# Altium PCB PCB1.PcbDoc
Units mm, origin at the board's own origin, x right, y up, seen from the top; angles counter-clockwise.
Board outline 143.51 x 21.34 mm, 2 copper layers (Top Layer, Bottom Layer); 100 components, 175 nets, 474 pads, 153 vias.
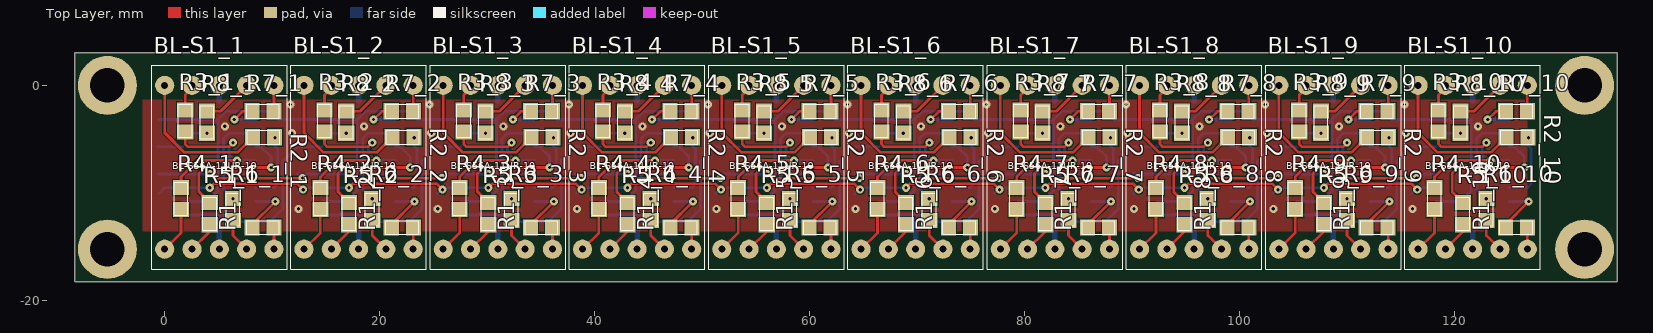
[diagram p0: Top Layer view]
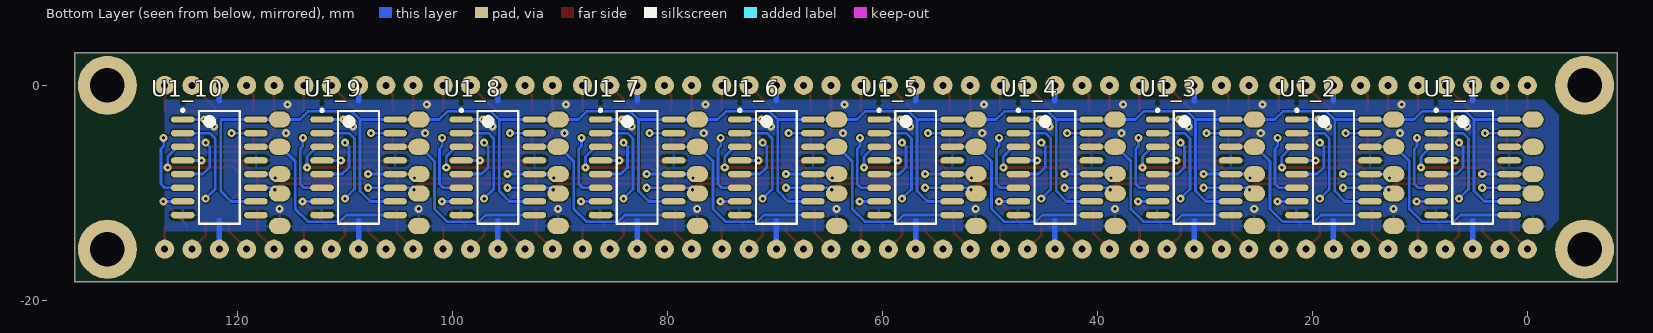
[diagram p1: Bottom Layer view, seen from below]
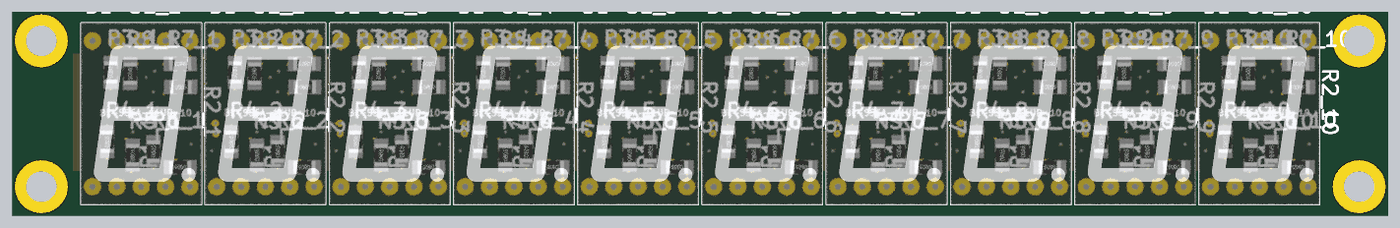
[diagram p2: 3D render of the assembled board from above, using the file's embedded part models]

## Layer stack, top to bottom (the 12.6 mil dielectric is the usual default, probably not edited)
Top Solder: solder mask 0.0102, Solder Resist, Dk 3.5
Top Layer: signal copper 0.0356
Dielectric 1: dielectric 0.32, FR-4, Dk 4.8
Bottom Layer: signal copper 0.0356
Bottom Solder: solder mask 0.0102, Solder Resist, Dk 3.5

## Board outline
-8.382,-18.288 -8.382,3.048 135.128,3.048 135.128,-18.288

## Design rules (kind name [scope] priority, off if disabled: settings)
Clearance [All] p1: gap=0.127
HoleSize [All] p1: absolutevalues=TRUE maxlimit=3.5 minlimit=0.025 maxpercent=80.000 minpercent=20.000
MinimumSolderMaskSliver [All] p1 off: minsoldermaskwidth=0.254
PolygonConnect toLEDS [HasFootprint('BL-S56A-11UR')] p1: connectstyle=Relief reliefconductorwidth=0.254 reliefentries=4 polygonreliefangle="45 Angle" airgapwidth=0.254
PolygonConnect toPADS [InPadClass('GND_PADS')] p2: connectstyle=Relief reliefconductorwidth=0.254 reliefentries=4 polygonreliefangle="90 Angle" airgapwidth=0.254
PolygonConnect toHC74 [HasFootprint('PRSP0016DH-B_N')] p3: connectstyle=Relief reliefconductorwidth=0.254 reliefentries=4 polygonreliefangle="90 Angle" airgapwidth=0.254
PolygonConnect [All] p4: connectstyle=Direct reliefconductorwidth=0.254 reliefentries=4 polygonreliefangle="90 Angle" airgapwidth=0.381
RoomDefinition 10 [InComponentClass('10')] p1: confinementstyle=ConfineIn formatcopy=TRUE lockcomponents=TRUE outline 114.935,-17.78 114.935,2.54 128.067,2.54 128.067,-17.78
RoomDefinition 9 [InComponentClass('9')] p2: confinementstyle=ConfineIn formatcopy=TRUE lockcomponents=TRUE outline 101.981,-17.78 101.981,2.54 115.113,2.54 115.113,-17.78
RoomDefinition 8 [InComponentClass('8')] p3: confinementstyle=ConfineIn formatcopy=TRUE lockcomponents=TRUE outline 89.027,-17.78 89.027,2.54 102.159,2.54 102.159,-17.78
RoomDefinition 7 [InComponentClass('7')] p4: confinementstyle=ConfineIn formatcopy=TRUE lockcomponents=TRUE outline 76.073,-17.78 76.073,2.54 89.205,2.54 89.205,-17.78
RoomDefinition 6 [InComponentClass('6')] p5: confinementstyle=ConfineIn formatcopy=TRUE lockcomponents=TRUE outline 63.119,-17.78 63.119,2.54 76.251,2.54 76.251,-17.78
RoomDefinition 5 [InComponentClass('5')] p6: confinementstyle=ConfineIn formatcopy=TRUE lockcomponents=TRUE outline 50.165,-17.78 50.165,2.54 63.297,2.54 63.297,-17.78
RoomDefinition 4 [InComponentClass('4')] p7: confinementstyle=ConfineIn formatcopy=TRUE lockcomponents=TRUE outline 37.211,-17.78 37.211,2.54 50.343,2.54 50.343,-17.78
RoomDefinition 2 [InComponentClass('2')] p8: confinementstyle=ConfineIn formatcopy=TRUE lockcomponents=FALSE outline 11.303,-17.78 11.303,2.54 24.435,2.54 24.435,-17.78
RoomDefinition 1 [InComponentClass('1')] p9: confinementstyle=ConfineIn formatcopy=TRUE lockcomponents=FALSE outline -1.651,-17.78 -1.651,2.54 11.481,2.54 11.481,-17.78
RoomDefinition 3 [InComponentClass('3')] p10: confinementstyle=ConfineIn formatcopy=TRUE lockcomponents=TRUE outline 24.257,-17.78 24.257,2.54 37.389,2.54 37.389,-17.78
RoutingVias [All] p1: holewidth=0.3 width=0.75 viastyle="Through Hole" minholewidth=0.3 minwidth=0.75 maxholewidth=0.711 maxwidth=1.778
SilkToBoardRegionClearance [All] p1 off:
SilkToSilkClearance [All] p1 off: silktosilkclearance=0.254
SilkToSolderMaskClearance [IsPad] p1 off: minsilkscreentomaskgap=0.254 clearancetoexposedcopper=TRUE
SolderMaskExpansion [All] p1: expansion=0.102
Width [All] p1: maxlimit=0.508 minlimit=0.2 preferedwidth=0.254
25 further rules are at their usual default settings.

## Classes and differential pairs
net class LEDS: L_A_1 L_A_2 L_A_3 L_A_4 L_A_5 L_A_6 L_A_7 L_A_8 L_A_9 L_A_10 L_B_1 L_B_2 L_B_3 L_B_4 L_B_5 L_B_6 L_B_7 L_B_8 L_B_9 L_B_10 L_C_1 L_C_2 L_C_3 L_C_4 L_C_5 L_C_6 L_C_7 L_C_8 L_C_9 L_C_10 L_D_1 L_D_2 L_D_3 L_D_4 L_D_5 L_D_6 L_D_7 L_D_8 L_D_9 L_D_10 L_E_1 L_E_2 L_E_3 L_E_4 L_E_5 L_E_6 L_E_7 L_E_8 L_E_9 L_E_10 L_F_1 L_F_2 L_F_3 L_F_4 L_F_5 L_F_6 L_F_7 L_F_8 L_F_9 L_F_10 L_G_1 L_G_2 L_G_3 L_G_4 L_G_5 L_G_6 L_G_7 L_G_8 L_G_9 L_G_10 L_H_1 L_H_2 L_H_3 L_H_4 L_H_5 L_H_6 L_H_7 L_H_8 L_H_9 L_H_10
component class 10: BL-S1_10 R1_10 R2_10 R3_10 R4_10 R5_10 R6_10 R7_10 R8_10 U1_10
component class 9: BL-S1_9 R1_9 R2_9 R3_9 R4_9 R5_9 R6_9 R7_9 R8_9 U1_9
component class 8: BL-S1_8 R1_8 R2_8 R3_8 R4_8 R5_8 R6_8 R7_8 R8_8 U1_8
component class 7: BL-S1_7 R1_7 R2_7 R3_7 R4_7 R5_7 R6_7 R7_7 R8_7 U1_7
channel class Sheet2: 1 2 3 4 5 6 7 8 9 10
component class 4: BL-S1_4 R1_4 R2_4 R3_4 R4_4 R5_4 R6_4 R7_4 R8_4 U1_4
component class 3: BL-S1_3 R1_3 R2_3 R3_3 R4_3 R5_3 R6_3 R7_3 R8_3 U1_3
component class 2: R1_2 R2_2 R3_2 R4_2 R5_2 R6_2 R7_2 R8_2 U1_2
component class 1: BL-S1_1 R1_1 R2_1 R3_1 R4_1 R5_1 R6_1 R7_1 R8_1 U1_1
component class 5: BL-S1_5 R1_5 R2_5 R3_5 R4_5 R5_5 R6_5 R7_5 R8_5 U1_5
component class 6: BL-S1_6 R1_6 R2_6 R3_6 R4_6 R5_6 R6_6 R7_6 R8_6 U1_6
pad class GND_PADS: Free-ref

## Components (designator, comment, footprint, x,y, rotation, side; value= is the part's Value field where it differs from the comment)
BL-S1_1 "BL-S56A-11UR" BL-S56A-11UR -1.22,-7.62 r0 top (schematic designator BL-S1)
BL-S1_2 "BL-S56A-11UR" BL-S56A-11UR 11.734,-7.62 r0 top (schematic designator BL-S1)
BL-S1_3 "BL-S56A-11UR" BL-S56A-11UR 24.688,-7.62 r0 top (schematic designator BL-S1)
BL-S1_4 "BL-S56A-11UR" BL-S56A-11UR 37.642,-7.62 r0 top (schematic designator BL-S1)
BL-S1_5 "BL-S56A-11UR" BL-S56A-11UR 50.596,-7.62 r0 top (schematic designator BL-S1)
BL-S1_6 "BL-S56A-11UR" BL-S56A-11UR 63.55,-7.62 r0 top (schematic designator BL-S1)
BL-S1_7 "BL-S56A-11UR" BL-S56A-11UR 76.504,-7.62 r0 top (schematic designator BL-S1)
BL-S1_8 "BL-S56A-11UR" BL-S56A-11UR 89.458,-7.62 r0 top (schematic designator BL-S1)
BL-S1_9 "BL-S56A-11UR" BL-S56A-11UR 102.412,-7.62 r0 top (schematic designator BL-S1)
BL-S1_10 "BL-S56A-11UR" BL-S56A-11UR 115.366,-7.62 r0 top (schematic designator BL-S1)
R1_1 "310R" Res0805 9.144,-13.208 r180 top (schematic designator R1)
R1_2 "310R" Res0805 22.098,-13.208 r180 top (schematic designator R1)
R1_3 "310R" Res0805 35.052,-13.208 r180 top (schematic designator R1)
R1_4 "310R" Res0805 48.006,-13.208 r180 top (schematic designator R1)
R1_5 "310R" Res0805 60.96,-13.208 r180 top (schematic designator R1)
R1_6 "310R" Res0805 73.914,-13.208 r180 top (schematic designator R1)
R1_7 "310R" Res0805 86.868,-13.208 r180 top (schematic designator R1)
R1_8 "310R" Res0805 99.822,-13.208 r180 top (schematic designator R1)
R1_9 "310R" Res0805 112.776,-13.208 r180 top (schematic designator R1)
R1_10 "310R" Res0805 125.73,-13.208 r180 top (schematic designator R1)
R2_1 "310R" Res0805 9.196,-4.826 r0 top (schematic designator R2)
R2_2 "310R" Res0805 22.15,-4.826 r0 top (schematic designator R2)
R2_3 "310R" Res0805 35.104,-4.826 r0 top (schematic designator R2)
R2_4 "310R" Res0805 48.058,-4.826 r0 top (schematic designator R2)
R2_5 "310R" Res0805 61.012,-4.826 r0 top (schematic designator R2)
R2_6 "310R" Res0805 73.966,-4.826 r0 top (schematic designator R2)
R2_7 "310R" Res0805 86.92,-4.826 r0 top (schematic designator R2)
R2_8 "310R" Res0805 99.874,-4.826 r0 top (schematic designator R2)
R2_9 "310R" Res0805 112.828,-4.826 r0 top (schematic designator R2)
R2_10 "310R" Res0805 125.782,-4.826 r0 top (schematic designator R2)
R3_1 "310R" Res0805 1.905,-3.302 r270 top (schematic designator R3)
R3_2 "310R" Res0805 14.859,-3.302 r270 top (schematic designator R3)
R3_3 "310R" Res0805 27.813,-3.302 r270 top (schematic designator R3)
R3_4 "310R" Res0805 40.767,-3.302 r270 top (schematic designator R3)
R3_5 "310R" Res0805 53.721,-3.302 r270 top (schematic designator R3)
R3_6 "310R" Res0805 66.675,-3.302 r270 top (schematic designator R3)
R3_7 "310R" Res0805 79.629,-3.302 r270 top (schematic designator R3)
R3_8 "310R" Res0805 92.583,-3.302 r270 top (schematic designator R3)
R3_9 "310R" Res0805 105.537,-3.302 r270 top (schematic designator R3)
R3_10 "310R" Res0805 118.491,-3.302 r270 top (schematic designator R3)
R4_1 "310R" Res0805 1.524,-10.541 r90 top (schematic designator R4)
R4_2 "310R" Res0805 14.478,-10.541 r90 top (schematic designator R4)
R4_3 "310R" Res0805 27.432,-10.541 r90 top (schematic designator R4)
R4_4 "310R" Res0805 40.386,-10.541 r90 top (schematic designator R4)
R4_5 "310R" Res0805 53.34,-10.541 r90 top (schematic designator R4)
R4_6 "310R" Res0805 66.294,-10.541 r90 top (schematic designator R4)
R4_7 "310R" Res0805 79.248,-10.541 r90 top (schematic designator R4)
R4_8 "310R" Res0805 92.202,-10.541 r90 top (schematic designator R4)
R4_9 "310R" Res0805 105.156,-10.541 r90 top (schematic designator R4)
R4_10 "310R" Res0805 118.11,-10.541 r90 top (schematic designator R4)
R5_1 "310R" Res0805 4.191,-11.938 r90 top (schematic designator R5)
R5_2 "310R" Res0805 17.145,-11.938 r90 top (schematic designator R5)
R5_3 "310R" Res0805 30.099,-11.938 r90 top (schematic designator R5)
R5_4 "310R" Res0805 43.053,-11.938 r90 top (schematic designator R5)
R5_5 "310R" Res0805 56.007,-11.938 r90 top (schematic designator R5)
R5_6 "310R" Res0805 68.961,-11.938 r90 top (schematic designator R5)
R5_7 "310R" Res0805 81.915,-11.938 r90 top (schematic designator R5)
R5_8 "310R" Res0805 94.869,-11.938 r90 top (schematic designator R5)
R5_9 "310R" Res0805 107.823,-11.938 r90 top (schematic designator R5)
R5_10 "310R" Res0805 120.777,-11.938 r90 top (schematic designator R5)
R6_1 "310R" Res0805 6.35,-11.557 r90 top (schematic designator R6)
R6_2 "310R" Res0805 19.304,-11.557 r90 top (schematic designator R6)
R6_3 "310R" Res0805 32.258,-11.557 r90 top (schematic designator R6)
R6_4 "310R" Res0805 45.212,-11.557 r90 top (schematic designator R6)
R6_5 "310R" Res0805 58.166,-11.557 r90 top (schematic designator R6)
R6_6 "310R" Res0805 71.12,-11.557 r90 top (schematic designator R6)
R6_7 "310R" Res0805 84.074,-11.557 r90 top (schematic designator R6)
R6_8 "310R" Res0805 97.028,-11.557 r90 top (schematic designator R6)
R6_9 "310R" Res0805 109.982,-11.557 r90 top (schematic designator R6)
R6_10 "310R" Res0805 122.936,-11.557 r90 top (schematic designator R6)
R7_1 "310R" Res0805 9.144,-2.413 r180 top (schematic designator R7)
R7_2 "310R" Res0805 22.098,-2.413 r180 top (schematic designator R7)
R7_3 "310R" Res0805 35.052,-2.413 r180 top (schematic designator R7)
R7_4 "310R" Res0805 48.006,-2.413 r180 top (schematic designator R7)
R7_5 "310R" Res0805 60.96,-2.413 r180 top (schematic designator R7)
R7_6 "310R" Res0805 73.914,-2.413 r180 top (schematic designator R7)
R7_7 "310R" Res0805 86.868,-2.413 r180 top (schematic designator R7)
R7_8 "310R" Res0805 99.822,-2.413 r180 top (schematic designator R7)
R7_9 "310R" Res0805 112.776,-2.413 r180 top (schematic designator R7)
R7_10 "310R" Res0805 125.73,-2.413 r180 top (schematic designator R7)
R8_1 "310R" Res0805 3.937,-3.429 r270 top (schematic designator R8)
R8_2 "310R" Res0805 16.891,-3.429 r270 top (schematic designator R8)
R8_3 "310R" Res0805 29.845,-3.429 r270 top (schematic designator R8)
R8_4 "310R" Res0805 42.799,-3.429 r270 top (schematic designator R8)
R8_5 "310R" Res0805 55.753,-3.429 r270 top (schematic designator R8)
R8_6 "310R" Res0805 68.707,-3.429 r270 top (schematic designator R8)
R8_7 "310R" Res0805 81.661,-3.429 r270 top (schematic designator R8)
R8_8 "310R" Res0805 94.615,-3.429 r270 top (schematic designator R8)
R8_9 "310R" Res0805 107.569,-3.429 r270 top (schematic designator R8)
R8_10 "310R" Res0805 120.523,-3.429 r270 top (schematic designator R8)
U1_1 "HD74HC595FP" PRSP0016DH-B_N 5.08,-7.62 r180 bottom (schematic designator U1)
U1_2 "HD74HC595FP" PRSP0016DH-B_N 18.034,-7.62 r180 bottom (schematic designator U1)
U1_3 "HD74HC595FP" PRSP0016DH-B_N 30.988,-7.62 r180 bottom (schematic designator U1)
U1_4 "HD74HC595FP" PRSP0016DH-B_N 43.942,-7.62 r180 bottom (schematic designator U1)
U1_5 "HD74HC595FP" PRSP0016DH-B_N 56.896,-7.62 r180 bottom (schematic designator U1)
U1_6 "HD74HC595FP" PRSP0016DH-B_N 69.85,-7.62 r180 bottom (schematic designator U1)
U1_7 "HD74HC595FP" PRSP0016DH-B_N 82.804,-7.62 r180 bottom (schematic designator U1)
U1_8 "HD74HC595FP" PRSP0016DH-B_N 95.758,-7.62 r180 bottom (schematic designator U1)
U1_9 "HD74HC595FP" PRSP0016DH-B_N 108.712,-7.62 r180 bottom (schematic designator U1)
U1_10 "HD74HC595FP" PRSP0016DH-B_N 121.666,-7.62 r180 bottom (schematic designator U1)

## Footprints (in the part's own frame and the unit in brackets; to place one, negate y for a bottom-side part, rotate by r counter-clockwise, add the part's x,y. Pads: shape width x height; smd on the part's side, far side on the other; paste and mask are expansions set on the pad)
BL-S56A-11UR [mm]
  round 1.778 hole 0.65: 1(1.22,-7.62) 2(3.76,-7.62) 3(6.3,-7.62) 4(8.84,-7.62) 5(11.38,-7.62) 6(11.38,7.62) 7(8.84,7.62) 8(6.3,7.62) 9(3.76,7.62) 10(1.22,7.62)
  silkscreen extent 0,-9.5 12.6,9.5, body extent 0,-9.5 12.6,9.5, height 8
PRSP0016DH-B_N [mm] "SOP, 16-Leads, Body 10.06x5.5mm, Pitch 1.27mm, IPC Medium Density"
  oval 2.2x0.6 smd: 1(-3.4,4.445) 2(-3.4,3.175) 3(-3.4,1.905) 4(-3.4,0.635) 5(-3.4,-0.635) 6(-3.4,-1.905) 7(-3.4,-3.175) 8(-3.4,-4.445) 9(3.4,-4.445) 10(3.4,-3.175) 11(3.4,-1.905) 12(3.4,-0.635) 13(3.4,0.635) 14(3.4,1.905) 15(3.4,3.175) 16(3.4,4.445)
  silkscreen extent -3.52,-5.25 1.9,5.42, body extent -2.7,-5.25 2.7,5.25, height 2.2
Res0805 [mm]
  rect 1.4x1.5 smd: 1(-1.025,0) 2(1.025,0)
  silkscreen extent -1.52,-0.64 1.52,0.64, body extent -1.15,-0.67 1.15,0.68, height 0.76

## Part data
BL-S1_1 BL-S1_2 BL-S1_3 BL-S1_4 BL-S1_5 BL-S1_6 BL-S1_7 BL-S1_8 BL-S1_9 BL-S1_10: library part Component_1
R1_1 R1_2 R1_3 R1_4 R1_5 R1_6 R1_7 R1_8 R1_9 R1_10 R2_1 R2_2 R2_3 R2_4 R2_5 R2_6 R2_7 R2_8 R2_9 R2_10 R3_1 R3_2 R3_3 R3_4 R3_5 R3_6 R3_7 R3_8 R3_9 R3_10 R4_1 R4_2 R4_3 R4_4 R4_5 R4_6 R4_7 R4_8 R4_9 R4_10 R5_1 R5_2 R5_3 R5_4 R5_5 R5_6 R5_7 R5_8 R5_9 R5_10 R6_1 R6_2 R6_3 R6_4 R6_5 R6_6 R6_7 R6_8 R6_9 R6_10 R7_1 R7_2 R7_3 R7_4 R7_5 R7_6 R7_7 R7_8 R7_9 R7_10 R8_1 R8_2 R8_3 R8_4 R8_5 R8_6 R8_7 R8_8 R8_9 R8_10: library part Res1, "Resistor"
U1_1 U1_2 U1_3 U1_4 U1_5 U1_6 U1_7 U1_8 U1_9 U1_10: "8-bit Shift Register / Latch with 3-State Outputs"

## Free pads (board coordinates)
  oval 2x1.5 smd far side: 8(-0.532,-3.175) 8(12.422,-3.175) 8(25.376,-3.175) 8(38.33,-3.175) 8(51.284,-3.175) 8(64.238,-3.175) 8(77.192,-3.175) 8(90.146,-3.175) 8(103.1,-3.175) 8(116.054,-3.175) 9(-0.532,-5.715) 9(12.422,-5.715) 9(25.376,-5.715) 9(38.33,-5.715) 9(51.284,-5.715) 9(64.238,-5.715) 9(77.192,-5.715) 9(90.146,-5.715) 9(103.1,-5.715) 9(116.054,-5.715) 10(-0.532,-8.255) 10(12.422,-8.255) 10(25.376,-8.255) 10(38.33,-8.255) 10(51.284,-8.255) 10(64.238,-8.255) 10(77.192,-8.255) 10(90.146,-8.255) 10(103.1,-8.255) 10(116.054,-8.255) 11(-0.533,-10.058) 11(12.421,-10.058) 11(25.375,-10.058) 11(38.329,-10.058) 11(51.283,-10.058) 11(64.237,-10.058) 11(77.191,-10.058) 11(90.145,-10.058) 11(103.099,-10.058) 11(116.053,-10.058) ref(-0.533,-13.081) ref(12.421,-13.081) ref(25.375,-13.081) ref(38.329,-13.081) ref(51.283,-13.081) ref(64.237,-13.081) ref(77.191,-13.081) ref(90.145,-13.081) ref(103.099,-13.081) ref(116.053,-13.081)
  round 5.5 hole 3.2: 12(-5.334,-15.24) 12(-5.334,0) 12(132.08,-15.24) 12(132.08,0)

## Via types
v1: diameter 0.75, hole 0.3, Top Layer to Bottom Layer, tented both sides, 135 vias
v2: diameter 0.75, hole 0.3, Top Layer to Bottom Layer, 18 vias

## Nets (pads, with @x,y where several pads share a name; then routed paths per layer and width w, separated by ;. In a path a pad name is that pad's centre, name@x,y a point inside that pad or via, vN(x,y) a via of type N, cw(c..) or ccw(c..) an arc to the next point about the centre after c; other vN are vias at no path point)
+5V: pad.8 U1_1.10 U1_1.16 U1_2.10 U1_2.16 U1_3.10 U1_3.16 U1_4.10 U1_4.16 U1_5.10 U1_5.16 U1_6.10 U1_6.16 U1_7.10 U1_7.16 U1_8.10 U1_8.16 U1_9.10 U1_9.16 U1_10.10 U1_10.16 | length 244.3
  Bottom Layer w0.254: pad.8@-0.532,-3.175 U1_1.16 4.953,-3.175 5.715,-2.413 9.779,-2.413 10.541,-3.175 U1_2.16 ; U1_1.10 3.99,-10.795 4.947,-9.838 4.947,-3.175 ; pad.8@12.422,-3.175 U1_2.16 ; U1_2.10 16.944,-10.795 17.901,-9.838 17.901,-3.175 ; U1_3.10 29.898,-10.795 30.855,-9.838 30.855,-3.175 ; U1_4.10 42.852,-10.795 43.809,-9.838 43.809,-3.175 ; U1_5.10 55.806,-10.795 56.763,-9.838 56.763,-3.175 ; pad.8@64.238,-3.175 69.723,-3.175 70.485,-2.413 74.549,-2.413 75.311,-3.175 U1_7.16 ; U1_6.10 68.76,-10.795 69.717,-9.838 69.717,-3.175 ; U1_6.16 62.357,-3.175 61.595,-2.413 57.531,-2.413 56.769,-3.175 51.284,-3.175 49.403,-3.175 48.641,-2.413 44.577,-2.413 43.815,-3.175 U1_4.16 38.33,-3.175 36.449,-3.175 35.687,-2.413 31.623,-2.413 30.861,-3.175 U1_3.16 25.376,-3.175 23.495,-3.175 22.733,-2.413 18.669,-2.413 17.907,-3.175 U1_2.16 ; pad.8@77.192,-3.175 82.677,-3.175 83.439,-2.413 87.503,-2.413 88.265,-3.175 U1_8.16 ; U1_7.10 81.714,-10.795 82.671,-9.838 82.671,-3.175 ; pad.8@90.146,-3.175 95.631,-3.175 96.393,-2.413 100.457,-2.413 101.219,-3.175 U1_9.16 ; U1_8.10 94.668,-10.795 95.625,-9.838 95.625,-3.175 ; pad.8@103.1,-3.175 108.585,-3.175 109.347,-2.413 113.411,-2.413 114.173,-3.175 U1_10.16 ; U1_9.10 107.622,-10.795 108.579,-9.838 108.579,-3.175 ; pad.8@116.054,-3.175 121.539,-3.175 ; U1_10.10 120.576,-10.795 121.533,-9.838 121.533,-3.175
GND: BL-S1_1.3 BL-S1_1.8 BL-S1_2.3 BL-S1_2.8 BL-S1_3.3 BL-S1_3.8 BL-S1_4.3 BL-S1_4.8 BL-S1_5.3 BL-S1_5.8 BL-S1_6.3 BL-S1_6.8 BL-S1_7.3 BL-S1_7.8 BL-S1_8.3 BL-S1_8.8 BL-S1_9.3 BL-S1_9.8 BL-S1_10.3 BL-S1_10.8 pad.ref U1_1.8 U1_1.13 U1_2.8 U1_2.13 U1_3.8 U1_3.13 U1_4.8 U1_4.13 U1_5.8 U1_5.13 U1_6.8 U1_6.13 U1_7.8 U1_7.13 U1_8.8 U1_8.13 U1_9.8 U1_9.13 U1_10.8 U1_10.13 | length 40.9
  Bottom Layer w0.508: BL-S1_1.3 5.08,-12.573 ; 5.08,-1.422 BL-S1_1.8 ; BL-S1_2.3 18.034,-12.573 ; 18.034,-1.422 BL-S1_2.8 ; BL-S1_3.3 30.988,-12.573 ; 30.988,-1.422 BL-S1_3.8 ; BL-S1_4.3 43.942,-12.573 ; 43.942,-1.422 BL-S1_4.8 ; BL-S1_5.3 56.896,-12.573 ; 56.896,-1.422 BL-S1_5.8 ; BL-S1_6.3 69.85,-12.573 ; 69.85,-1.422 BL-S1_6.8 ; BL-S1_7.3 82.804,-12.573 ; 82.804,-1.422 BL-S1_7.8 ; BL-S1_8.3 95.758,-12.573 ; 95.758,-1.422 BL-S1_8.8 ; BL-S1_9.3 108.712,-12.573 ; 108.712,-1.422 BL-S1_9.8 ; BL-S1_10.3 121.666,-12.573 ; 121.666,-1.422 BL-S1_10.8
  other v1: 12.446,-11.481 25.4,-11.481 38.354,-11.481 51.308,-11.481 64.262,-11.481 77.216,-11.481 90.17,-11.481 103.124,-11.481 116.078,-11.481 11.836,-4.445 24.79,-4.445 37.744,-4.445 50.698,-4.445 63.652,-4.445 76.606,-4.445 89.56,-4.445 102.514,-4.445 115.468,-4.445 5.588,-3.81 18.542,-3.81 31.496,-3.81 44.45,-3.81 57.404,-3.81 70.358,-3.81 83.312,-3.81 96.266,-3.81 109.22,-3.81 122.174,-3.81 11.684,-1.778 24.638,-1.778 37.592,-1.778 50.546,-1.778 63.5,-1.778 76.454,-1.778 89.408,-1.778 102.362,-1.778 115.316,-1.778
L_A_1: BL-S1_1.7 R8_1.1 | length 4.7
  Top Layer w0.254: R8_1.1 5.216,-2.404 BL-S1_1.7
L_A_2: BL-S1_2.7 R8_2.1 | length 4.7
  Top Layer w0.254: R8_2.1 18.17,-2.404 BL-S1_2.7
L_A_3: BL-S1_3.7 R8_3.1 | length 4.7
  Top Layer w0.254: R8_3.1 31.124,-2.404 BL-S1_3.7
L_A_4: BL-S1_4.7 R8_4.1 | length 4.7
  Top Layer w0.254: R8_4.1 44.078,-2.404 BL-S1_4.7
L_A_5: BL-S1_5.7 R8_5.1 | length 4.7
  Top Layer w0.254: R8_5.1 57.032,-2.404 BL-S1_5.7
L_A_6: BL-S1_6.7 R8_6.1 | length 4.7
  Top Layer w0.254: R8_6.1 69.986,-2.404 BL-S1_6.7
L_A_7: BL-S1_7.7 R8_7.1 | length 4.7
  Top Layer w0.254: R8_7.1 82.94,-2.404 BL-S1_7.7
L_A_8: BL-S1_8.7 R8_8.1 | length 4.7
  Top Layer w0.254: R8_8.1 95.894,-2.404 BL-S1_8.7
L_A_9: BL-S1_9.7 R8_9.1 | length 4.7
  Top Layer w0.254: R8_9.1 108.848,-2.404 BL-S1_9.7
L_A_10: BL-S1_10.7 R8_10.1 | length 4.7
  Top Layer w0.254: R8_10.1 121.802,-2.404 BL-S1_10.7
L_B_1: BL-S1_1.6 R7_1.1 | length 2.4
  Top Layer w0.254: BL-S1_1.6 10.169,-0.009 R7_1.1
L_B_2: BL-S1_2.6 R7_2.1 | length 2.4
  Top Layer w0.254: BL-S1_2.6 23.123,-0.009 R7_2.1
L_B_3: BL-S1_3.6 R7_3.1 | length 2.4
  Top Layer w0.254: BL-S1_3.6 36.077,-0.009 R7_3.1
L_B_4: BL-S1_4.6 R7_4.1 | length 2.4
  Top Layer w0.254: BL-S1_4.6 49.031,-0.009 R7_4.1
L_B_5: BL-S1_5.6 R7_5.1 | length 2.4
  Top Layer w0.254: BL-S1_5.6 61.985,-0.009 R7_5.1
L_B_6: BL-S1_6.6 R7_6.1 | length 2.4
  Top Layer w0.254: BL-S1_6.6 74.939,-0.009 R7_6.1
L_B_7: BL-S1_7.6 R7_7.1 | length 2.4
  Top Layer w0.254: BL-S1_7.6 87.893,-0.009 R7_7.1
L_B_8: BL-S1_8.6 R7_8.1 | length 2.4
  Top Layer w0.254: BL-S1_8.6 100.847,-0.009 R7_8.1
L_B_9: BL-S1_9.6 R7_9.1 | length 2.4
  Top Layer w0.254: BL-S1_9.6 113.801,-0.009 R7_9.1
L_B_10: BL-S1_10.6 R7_10.1 | length 2.4
  Top Layer w0.254: BL-S1_10.6 126.755,-0.009 R7_10.1
L_C_1: BL-S1_1.4 R6_1.1 | length 3.2
  Top Layer w0.254: R6_1.1 6.35,-13.97 BL-S1_1.4
L_C_2: BL-S1_2.4 R6_2.1 | length 3.2
  Top Layer w0.254: R6_2.1 19.304,-13.97 BL-S1_2.4
L_C_3: BL-S1_3.4 R6_3.1 | length 3.2
  Top Layer w0.254: R6_3.1 32.258,-13.97 BL-S1_3.4
L_C_4: BL-S1_4.4 R6_4.1 | length 3.2
  Top Layer w0.254: R6_4.1 45.212,-13.97 BL-S1_4.4
L_C_5: BL-S1_5.4 R6_5.1 | length 3.2
  Top Layer w0.254: R6_5.1 58.166,-13.97 BL-S1_5.4
L_C_6: BL-S1_6.4 R6_6.1 | length 3.2
  Top Layer w0.254: R6_6.1 71.12,-13.97 BL-S1_6.4
L_C_7: BL-S1_7.4 R6_7.1 | length 3.2
  Top Layer w0.254: R6_7.1 84.074,-13.97 BL-S1_7.4
L_C_8: BL-S1_8.4 R6_8.1 | length 3.2
  Top Layer w0.254: R6_8.1 97.028,-13.97 BL-S1_8.4
L_C_9: BL-S1_9.4 R6_9.1 | length 3.2
  Top Layer w0.254: R6_9.1 109.982,-13.97 BL-S1_9.4
L_C_10: BL-S1_10.4 R6_10.1 | length 3.2
  Top Layer w0.254: R6_10.1 122.936,-13.97 BL-S1_10.4
L_D_1: BL-S1_1.2 R5_1.1 | length 2.8
  Top Layer w0.254: BL-S1_1.2 4.191,-13.589 R5_1.1@4.191,-13.09
L_D_2: BL-S1_2.2 R5_2.1 | length 2.8
  Top Layer w0.254: BL-S1_2.2 17.145,-13.589 R5_2.1@17.145,-13.09
L_D_3: BL-S1_3.2 R5_3.1 | length 2.8
  Top Layer w0.254: BL-S1_3.2 30.099,-13.589 R5_3.1@30.099,-13.09
L_D_4: BL-S1_4.2 R5_4.1 | length 2.8
  Top Layer w0.254: BL-S1_4.2 43.053,-13.589 R5_4.1@43.053,-13.09
L_D_5: BL-S1_5.2 R5_5.1 | length 2.8
  Top Layer w0.254: BL-S1_5.2 56.007,-13.589 R5_5.1@56.007,-13.09
L_D_6: BL-S1_6.2 R5_6.1 | length 2.8
  Top Layer w0.254: BL-S1_6.2 68.961,-13.589 R5_6.1@68.961,-13.09
L_D_7: BL-S1_7.2 R5_7.1 | length 2.8
  Top Layer w0.254: BL-S1_7.2 81.915,-13.589 R5_7.1@81.915,-13.09
L_D_8: BL-S1_8.2 R5_8.1 | length 2.8
  Top Layer w0.254: BL-S1_8.2 94.869,-13.589 R5_8.1@94.869,-13.09
L_D_9: BL-S1_9.2 R5_9.1 | length 2.8
  Top Layer w0.254: BL-S1_9.2 107.823,-13.589 R5_9.1@107.823,-13.09
L_D_10: BL-S1_10.2 R5_10.1 | length 2.8
  Top Layer w0.254: BL-S1_10.2 120.777,-13.589 R5_10.1@120.777,-13.09
L_E_1: BL-S1_1.1 R4_1.1 | length 4.3
  Top Layer w0.254: BL-S1_1.1 1.524,-13.716 R4_1.1
L_E_2: BL-S1_2.1 R4_2.1 | length 4.3
  Top Layer w0.254: BL-S1_2.1 14.478,-13.716 R4_2.1
L_E_3: BL-S1_3.1 R4_3.1 | length 4.3
  Top Layer w0.254: BL-S1_3.1 27.432,-13.716 R4_3.1
L_E_4: BL-S1_4.1 R4_4.1 | length 4.3
  Top Layer w0.254: BL-S1_4.1 40.386,-13.716 R4_4.1
L_E_5: BL-S1_5.1 R4_5.1 | length 4.3
  Top Layer w0.254: BL-S1_5.1 53.34,-13.716 R4_5.1
L_E_6: BL-S1_6.1 R4_6.1 | length 4.3
  Top Layer w0.254: BL-S1_6.1 66.294,-13.716 R4_6.1
L_E_7: BL-S1_7.1 R4_7.1 | length 4.3
  Top Layer w0.254: BL-S1_7.1 79.248,-13.716 R4_7.1
L_E_8: BL-S1_8.1 R4_8.1 | length 4.3
  Top Layer w0.254: BL-S1_8.1 92.202,-13.716 R4_8.1
L_E_9: BL-S1_9.1 R4_9.1 | length 4.3
  Top Layer w0.254: BL-S1_9.1 105.156,-13.716 R4_9.1
L_E_10: BL-S1_10.1 R4_10.1 | length 4.3
  Top Layer w0.254: BL-S1_10.1 118.11,-13.716 R4_10.1
L_F_1: BL-S1_1.9 R3_1.1 | length 2.5
  Top Layer w0.254: R3_1.1 1.905,-0.889 2.54,-0.254 BL-S1_1.9
L_F_2: BL-S1_2.9 R3_2.1 | length 2.5
  Top Layer w0.254: R3_2.1 14.859,-0.889 15.494,-0.254 BL-S1_2.9
L_F_3: BL-S1_3.9 R3_3.1 | length 2.5
  Top Layer w0.254: R3_3.1 27.813,-0.889 28.448,-0.254 BL-S1_3.9
L_F_4: BL-S1_4.9 R3_4.1 | length 2.5
  Top Layer w0.254: R3_4.1 40.767,-0.889 41.402,-0.254 BL-S1_4.9
L_F_5: BL-S1_5.9 R3_5.1 | length 2.5
  Top Layer w0.254: R3_5.1 53.721,-0.889 54.356,-0.254 BL-S1_5.9
L_F_6: BL-S1_6.9 R3_6.1 | length 2.5
  Top Layer w0.254: R3_6.1 66.675,-0.889 67.31,-0.254 BL-S1_6.9
L_F_7: BL-S1_7.9 R3_7.1 | length 2.5
  Top Layer w0.254: R3_7.1 79.629,-0.889 80.264,-0.254 BL-S1_7.9
L_F_8: BL-S1_8.9 R3_8.1 | length 2.5
  Top Layer w0.254: R3_8.1 92.583,-0.889 93.218,-0.254 BL-S1_8.9
L_F_9: BL-S1_9.9 R3_9.1 | length 2.5
  Top Layer w0.254: R3_9.1 105.537,-0.889 106.172,-0.254 BL-S1_9.9
L_F_10: BL-S1_10.9 R3_10.1 | length 2.5
  Top Layer w0.254: R3_10.1 118.491,-0.889 119.126,-0.254 BL-S1_10.9
L_G_1: BL-S1_1.10 R2_1.1 | length 13.9
  Top Layer w0.254: BL-S1_1.10 0,-4.411 1.818,-6.229 6.768,-6.229 R2_1.1
L_G_2: BL-S1_2.10 R2_2.1 | length 13.9
  Top Layer w0.254: BL-S1_2.10 12.954,-4.411 14.772,-6.229 19.722,-6.229 R2_2.1
L_G_3: BL-S1_3.10 R2_3.1 | length 13.9
  Top Layer w0.254: BL-S1_3.10 25.908,-4.411 27.726,-6.229 32.676,-6.229 R2_3.1
L_G_4: BL-S1_4.10 R2_4.1 | length 13.9
  Top Layer w0.254: BL-S1_4.10 38.862,-4.411 40.68,-6.229 45.63,-6.229 R2_4.1
L_G_5: BL-S1_5.10 R2_5.1 | length 13.9
  Top Layer w0.254: BL-S1_5.10 51.816,-4.411 53.634,-6.229 58.584,-6.229 R2_5.1
L_G_6: BL-S1_6.10 R2_6.1 | length 13.9
  Top Layer w0.254: BL-S1_6.10 64.77,-4.411 66.588,-6.229 71.538,-6.229 R2_6.1
L_G_7: BL-S1_7.10 R2_7.1 | length 13.9
  Top Layer w0.254: BL-S1_7.10 77.724,-4.411 79.542,-6.229 84.492,-6.229 R2_7.1
L_G_8: BL-S1_8.10 R2_8.1 | length 13.9
  Top Layer w0.254: BL-S1_8.10 90.678,-4.411 92.496,-6.229 97.446,-6.229 R2_8.1
L_G_9: BL-S1_9.10 R2_9.1 | length 13.9
  Top Layer w0.254: BL-S1_9.10 103.632,-4.411 105.45,-6.229 110.4,-6.229 R2_9.1
L_G_10: BL-S1_10.10 R2_10.1 | length 13.9
  Top Layer w0.254: BL-S1_10.10 116.586,-4.411 118.404,-6.229 123.354,-6.229 R2_10.1
L_H_1: BL-S1_1.5 R1_1.1 | length 2
  Top Layer w0.254: BL-S1_1.5 10.169,-15.231 R1_1.1
L_H_2: BL-S1_2.5 R1_2.1 | length 2
  Top Layer w0.254: BL-S1_2.5 23.123,-15.231 R1_2.1
L_H_3: BL-S1_3.5 R1_3.1 | length 2
  Top Layer w0.254: BL-S1_3.5 36.077,-15.231 R1_3.1
L_H_4: BL-S1_4.5 R1_4.1 | length 2
  Top Layer w0.254: BL-S1_4.5 49.031,-15.231 R1_4.1
L_H_5: BL-S1_5.5 R1_5.1 | length 2
  Top Layer w0.254: BL-S1_5.5 61.985,-15.231 R1_5.1
L_H_6: BL-S1_6.5 R1_6.1 | length 2
  Top Layer w0.254: BL-S1_6.5 74.939,-15.231 R1_6.1
L_H_7: BL-S1_7.5 R1_7.1 | length 2
  Top Layer w0.254: BL-S1_7.5 87.893,-15.231 R1_7.1
L_H_8: BL-S1_8.5 R1_8.1 | length 2
  Top Layer w0.254: BL-S1_8.5 100.847,-15.231 R1_8.1
L_H_9: BL-S1_9.5 R1_9.1 | length 2
  Top Layer w0.254: BL-S1_9.5 113.801,-15.231 R1_9.1
L_H_10: BL-S1_10.5 R1_10.1 | length 2
  Top Layer w0.254: BL-S1_10.5 126.755,-15.231 R1_10.1
NetR1_1_2: R1_1.2 U1_1.7 | length 5.1
  Top Layer w0.254: R1_1.2 8.119,-12.963 v1(10.287,-10.795)
  Bottom Layer w0.254: U1_1.7 v1(10.287,-10.795)
NetR1_2_2: R1_2.2 U1_2.7 | length 5.1
  Top Layer w0.254: R1_2.2 21.073,-12.963 v1(23.241,-10.795)
  Bottom Layer w0.254: U1_2.7 v1(23.241,-10.795)
NetR1_3_2: R1_3.2 U1_3.7 | length 5.1
  Top Layer w0.254: R1_3.2 34.027,-12.963 v1(36.195,-10.795)
  Bottom Layer w0.254: U1_3.7 v1(36.195,-10.795)
NetR1_4_2: R1_4.2 U1_4.7 | length 5.1
  Top Layer w0.254: R1_4.2 46.981,-12.963 v1(49.149,-10.795)
  Bottom Layer w0.254: U1_4.7 v1(49.149,-10.795)
NetR1_5_2: R1_5.2 U1_5.7 | length 5.1
  Top Layer w0.254: R1_5.2 59.935,-12.963 v1(62.103,-10.795)
  Bottom Layer w0.254: U1_5.7 v1(62.103,-10.795)
NetR1_6_2: R1_6.2 U1_6.7 | length 5.1
  Top Layer w0.254: R1_6.2 72.889,-12.963 v1(75.057,-10.795)
  Bottom Layer w0.254: U1_6.7 v1(75.057,-10.795)
NetR1_7_2: R1_7.2 U1_7.7 | length 5.1
  Top Layer w0.254: R1_7.2 85.843,-12.963 v1(88.011,-10.795)
  Bottom Layer w0.254: U1_7.7 v1(88.011,-10.795)
NetR1_8_2: R1_8.2 U1_8.7 | length 5.1
  Top Layer w0.254: R1_8.2 98.797,-12.963 v1(100.965,-10.795)
  Bottom Layer w0.254: U1_8.7 v1(100.965,-10.795)
NetR1_9_2: R1_9.2 U1_9.7 | length 5.1
  Top Layer w0.254: R1_9.2 111.751,-12.963 v1(113.919,-10.795)
  Bottom Layer w0.254: U1_9.7 v1(113.919,-10.795)
NetR1_10_2: R1_10.2 U1_10.7 | length 5.1
  Top Layer w0.254: R1_10.2 124.705,-12.963 v1(126.873,-10.795)
  Bottom Layer w0.254: U1_10.7 v1(126.873,-10.795)
NetR2_1_2: R2_1.2 U1_1.6 | length 6.6
  Bottom Layer w0.254: U1_1.6 10.16,-9.525 10.51,-9.175 10.51,-5.907 10.262,-5.659 v1(10.262,-4.877)
NetR2_2_2: R2_2.2 U1_2.6 | length 6.6
  Bottom Layer w0.254: U1_2.6 23.114,-9.525 23.464,-9.175 23.464,-5.907 23.216,-5.659 v1(23.216,-4.877)
NetR2_3_2: R2_3.2 U1_3.6 | length 6.6
  Bottom Layer w0.254: U1_3.6 36.068,-9.525 36.418,-9.175 36.418,-5.907 36.17,-5.659 v1(36.17,-4.877)
NetR2_4_2: R2_4.2 U1_4.6 | length 6.6
  Bottom Layer w0.254: U1_4.6 49.022,-9.525 49.372,-9.175 49.372,-5.907 49.124,-5.659 v1(49.124,-4.877)
NetR2_5_2: R2_5.2 U1_5.6 | length 6.6
  Bottom Layer w0.254: U1_5.6 61.976,-9.525 62.326,-9.175 62.326,-5.907 62.078,-5.659 v1(62.078,-4.877)
NetR2_6_2: R2_6.2 U1_6.6 | length 6.6
  Bottom Layer w0.254: U1_6.6 74.93,-9.525 75.28,-9.175 75.28,-5.907 75.032,-5.659 v1(75.032,-4.877)
NetR2_7_2: R2_7.2 U1_7.6 | length 6.6
  Bottom Layer w0.254: U1_7.6 87.884,-9.525 88.234,-9.175 88.234,-5.907 87.986,-5.659 v1(87.986,-4.877)
NetR2_8_2: R2_8.2 U1_8.6 | length 6.6
  Bottom Layer w0.254: U1_8.6 100.838,-9.525 101.188,-9.175 101.188,-5.907 100.94,-5.659 v1(100.94,-4.877)
NetR2_9_2: R2_9.2 U1_9.6 | length 6.6
  Bottom Layer w0.254: U1_9.6 113.792,-9.525 114.142,-9.175 114.142,-5.907 113.894,-5.659 v1(113.894,-4.877)
NetR2_10_2: R2_10.2 U1_10.6 | length 6.6
  Bottom Layer w0.254: U1_10.6 126.746,-9.525 127.096,-9.175 127.096,-5.907 126.848,-5.659 v1(126.848,-4.877)
NetR3_1_2: R3_1.2 U1_1.5 | length 11.1
  Top Layer w0.254: R3_1.2 1.905,-5.461 2.159,-5.715 5.969,-5.715 v1(6.35,-5.334)
  Bottom Layer w0.254: v1(6.35,-5.334) 5.975,-5.709 5.975,-7.626 6.604,-8.255 U1_1.5
NetR3_2_2: R3_2.2 U1_2.5 | length 11.1
  Top Layer w0.254: R3_2.2 14.859,-5.461 15.113,-5.715 18.923,-5.715 v1(19.304,-5.334)
  Bottom Layer w0.254: v1(19.304,-5.334) 18.929,-5.709 18.929,-7.626 19.558,-8.255 U1_2.5
NetR3_3_2: R3_3.2 U1_3.5 | length 11.1
  Top Layer w0.254: R3_3.2 27.813,-5.461 28.067,-5.715 31.877,-5.715 v1(32.258,-5.334)
  Bottom Layer w0.254: v1(32.258,-5.334) 31.883,-5.709 31.883,-7.626 32.512,-8.255 U1_3.5
NetR3_4_2: R3_4.2 U1_4.5 | length 11.1
  Top Layer w0.254: R3_4.2 40.767,-5.461 41.021,-5.715 44.831,-5.715 v1(45.212,-5.334)
  Bottom Layer w0.254: v1(45.212,-5.334) 44.837,-5.709 44.837,-7.626 45.466,-8.255 U1_4.5
NetR3_5_2: R3_5.2 U1_5.5 | length 11.1
  Top Layer w0.254: R3_5.2 53.721,-5.461 53.975,-5.715 57.785,-5.715 v1(58.166,-5.334)
  Bottom Layer w0.254: v1(58.166,-5.334) 57.791,-5.709 57.791,-7.626 58.42,-8.255 U1_5.5
NetR3_6_2: R3_6.2 U1_6.5 | length 11.1
  Top Layer w0.254: R3_6.2 66.675,-5.461 66.929,-5.715 70.739,-5.715 v1(71.12,-5.334)
  Bottom Layer w0.254: v1(71.12,-5.334) 70.745,-5.709 70.745,-7.626 71.374,-8.255 U1_6.5
NetR3_7_2: R3_7.2 U1_7.5 | length 11.1
  Top Layer w0.254: R3_7.2 79.629,-5.461 79.883,-5.715 83.693,-5.715 v1(84.074,-5.334)
  Bottom Layer w0.254: v1(84.074,-5.334) 83.699,-5.709 83.699,-7.626 84.328,-8.255 U1_7.5
NetR3_8_2: R3_8.2 U1_8.5 | length 11.1
  Top Layer w0.254: R3_8.2 92.583,-5.461 92.837,-5.715 96.647,-5.715 v1(97.028,-5.334)
  Bottom Layer w0.254: v1(97.028,-5.334) 96.653,-5.709 96.653,-7.626 97.282,-8.255 U1_8.5
NetR3_9_2: R3_9.2 U1_9.5 | length 11.1
  Top Layer w0.254: R3_9.2 105.537,-5.461 105.791,-5.715 109.601,-5.715 v1(109.982,-5.334)
  Bottom Layer w0.254: v1(109.982,-5.334) 109.607,-5.709 109.607,-7.626 110.236,-8.255 U1_9.5
NetR3_10_2: R3_10.2 U1_10.5 | length 11.1
  Top Layer w0.254: R3_10.2 118.491,-5.461 118.745,-5.715 122.555,-5.715 v1(122.936,-5.334)
  Bottom Layer w0.254: v1(122.936,-5.334) 122.561,-5.709 122.561,-7.626 123.19,-8.255 U1_10.5
NetR4_1_2: R4_1.2 U1_1.4 | length 8.6
  Top Layer w0.254: R4_1.2 1.524,-8.509 3.048,-6.985 v1(6.731,-6.985)
  Bottom Layer w0.254: v1(6.731,-6.985) U1_1.4
NetR4_2_2: R4_2.2 U1_2.4 | length 8.6
  Top Layer w0.254: R4_2.2 14.478,-8.509 16.002,-6.985 v1(19.685,-6.985)
  Bottom Layer w0.254: v1(19.685,-6.985) U1_2.4
NetR4_3_2: R4_3.2 U1_3.4 | length 8.6
  Top Layer w0.254: R4_3.2 27.432,-8.509 28.956,-6.985 v1(32.639,-6.985)
  Bottom Layer w0.254: v1(32.639,-6.985) U1_3.4
NetR4_4_2: R4_4.2 U1_4.4 | length 8.6
  Top Layer w0.254: R4_4.2 40.386,-8.509 41.91,-6.985 v1(45.593,-6.985)
  Bottom Layer w0.254: v1(45.593,-6.985) U1_4.4
NetR4_5_2: R4_5.2 U1_5.4 | length 8.6
  Top Layer w0.254: R4_5.2 53.34,-8.509 54.864,-6.985 v1(58.547,-6.985)
  Bottom Layer w0.254: v1(58.547,-6.985) U1_5.4
NetR4_6_2: R4_6.2 U1_6.4 | length 8.6
  Top Layer w0.254: R4_6.2 66.294,-8.509 67.818,-6.985 v1(71.501,-6.985)
  Bottom Layer w0.254: v1(71.501,-6.985) U1_6.4
NetR4_7_2: R4_7.2 U1_7.4 | length 8.6
  Top Layer w0.254: R4_7.2 79.248,-8.509 80.772,-6.985 v1(84.455,-6.985)
  Bottom Layer w0.254: v1(84.455,-6.985) U1_7.4
NetR4_8_2: R4_8.2 U1_8.4 | length 8.6
  Top Layer w0.254: R4_8.2 92.202,-8.509 93.726,-6.985 v1(97.409,-6.985)
  Bottom Layer w0.254: v1(97.409,-6.985) U1_8.4
NetR4_9_2: R4_9.2 U1_9.4 | length 8.6
  Top Layer w0.254: R4_9.2 105.156,-8.509 106.68,-6.985 v1(110.363,-6.985)
  Bottom Layer w0.254: v1(110.363,-6.985) U1_9.4
NetR4_10_2: R4_10.2 U1_10.4 | length 8.6
  Top Layer w0.254: R4_10.2 118.11,-8.509 119.634,-6.985 v1(123.317,-6.985)
  Bottom Layer w0.254: v1(123.317,-6.985) U1_10.4
NetR5_1_2: R5_1.2 U1_1.3 | length 13
  Top Layer w0.254: R5_1.2 3.175,-9.897 3.175,-8.202 3.884,-7.493 4.445,-7.493 4.597,-7.645 v1(9.881,-7.645)
  Bottom Layer w0.254: U1_1.3 8.966,-5.715 9.881,-6.629 v1(9.881,-7.645)
NetR5_2_2: R5_2.2 U1_2.3 | length 13
  Top Layer w0.254: R5_2.2 16.129,-9.897 16.129,-8.202 16.838,-7.493 17.399,-7.493 17.551,-7.645 v1(22.835,-7.645)
  Bottom Layer w0.254: U1_2.3 21.92,-5.715 22.835,-6.629 v1(22.835,-7.645)
NetR5_3_2: R5_3.2 U1_3.3 | length 13
  Top Layer w0.254: R5_3.2 29.083,-9.897 29.083,-8.202 29.792,-7.493 30.353,-7.493 30.505,-7.645 v1(35.789,-7.645)
  Bottom Layer w0.254: U1_3.3 34.874,-5.715 35.789,-6.629 v1(35.789,-7.645)
NetR5_4_2: R5_4.2 U1_4.3 | length 13
  Top Layer w0.254: R5_4.2 42.037,-9.897 42.037,-8.202 42.746,-7.493 43.307,-7.493 43.459,-7.645 v1(48.743,-7.645)
  Bottom Layer w0.254: U1_4.3 47.828,-5.715 48.743,-6.629 v1(48.743,-7.645)
NetR5_5_2: R5_5.2 U1_5.3 | length 13
  Top Layer w0.254: R5_5.2 54.991,-9.897 54.991,-8.202 55.7,-7.493 56.261,-7.493 56.413,-7.645 v1(61.697,-7.645)
  Bottom Layer w0.254: U1_5.3 60.782,-5.715 61.697,-6.629 v1(61.697,-7.645)
NetR5_6_2: R5_6.2 U1_6.3 | length 13
  Top Layer w0.254: R5_6.2 67.945,-9.897 67.945,-8.202 68.654,-7.493 69.215,-7.493 69.367,-7.645 v1(74.651,-7.645)
  Bottom Layer w0.254: U1_6.3 73.736,-5.715 74.651,-6.629 v1(74.651,-7.645)
NetR5_7_2: R5_7.2 U1_7.3 | length 13
  Top Layer w0.254: R5_7.2 80.899,-9.897 80.899,-8.202 81.608,-7.493 82.169,-7.493 82.321,-7.645 v1(87.605,-7.645)
  Bottom Layer w0.254: U1_7.3 86.69,-5.715 87.605,-6.629 v1(87.605,-7.645)
NetR5_8_2: R5_8.2 U1_8.3 | length 13
  Top Layer w0.254: R5_8.2 93.853,-9.897 93.853,-8.202 94.562,-7.493 95.123,-7.493 95.275,-7.645 v1(100.559,-7.645)
  Bottom Layer w0.254: U1_8.3 99.644,-5.715 100.559,-6.629 v1(100.559,-7.645)
NetR5_9_2: R5_9.2 U1_9.3 | length 13
  Top Layer w0.254: R5_9.2 106.807,-9.897 106.807,-8.202 107.516,-7.493 108.077,-7.493 108.229,-7.645 v1(113.513,-7.645)
  Bottom Layer w0.254: U1_9.3 112.598,-5.715 113.513,-6.629 v1(113.513,-7.645)
NetR5_10_2: R5_10.2 U1_10.3 | length 13
  Top Layer w0.254: R5_10.2 119.761,-9.897 119.761,-8.202 120.47,-7.493 121.031,-7.493 121.183,-7.645 v1(126.467,-7.645)
  Bottom Layer w0.254: U1_10.3 125.552,-5.715 126.467,-6.629 v1(126.467,-7.645)
NetR6_1_2: R6_1.2 U1_1.2 | length 9.2
  Top Layer w0.254: v1(6.35,-10.541) R6_1.2
  Bottom Layer w0.254: v1(6.35,-10.541) 5.461,-9.652 5.461,-4.953 5.969,-4.445 U1_1.2
NetR6_2_2: R6_2.2 U1_2.2 | length 9.2
  Top Layer w0.254: v1(19.304,-10.541) R6_2.2
  Bottom Layer w0.254: v1(19.304,-10.541) 18.415,-9.652 18.415,-4.953 18.923,-4.445 U1_2.2
NetR6_3_2: R6_3.2 U1_3.2 | length 9.2
  Top Layer w0.254: v1(32.258,-10.541) R6_3.2
  Bottom Layer w0.254: v1(32.258,-10.541) 31.369,-9.652 31.369,-4.953 31.877,-4.445 U1_3.2
NetR6_4_2: R6_4.2 U1_4.2 | length 9.2
  Top Layer w0.254: v1(45.212,-10.541) R6_4.2
  Bottom Layer w0.254: v1(45.212,-10.541) 44.323,-9.652 44.323,-4.953 44.831,-4.445 U1_4.2
NetR6_5_2: R6_5.2 U1_5.2 | length 9.2
  Top Layer w0.254: v1(58.166,-10.541) R6_5.2
  Bottom Layer w0.254: v1(58.166,-10.541) 57.277,-9.652 57.277,-4.953 57.785,-4.445 U1_5.2
NetR6_6_2: R6_6.2 U1_6.2 | length 9.2
  Top Layer w0.254: v1(71.12,-10.541) R6_6.2
  Bottom Layer w0.254: v1(71.12,-10.541) 70.231,-9.652 70.231,-4.953 70.739,-4.445 U1_6.2
NetR6_7_2: R6_7.2 U1_7.2 | length 9.2
  Top Layer w0.254: v1(84.074,-10.541) R6_7.2
  Bottom Layer w0.254: v1(84.074,-10.541) 83.185,-9.652 83.185,-4.953 83.693,-4.445 U1_7.2
NetR6_8_2: R6_8.2 U1_8.2 | length 9.2
  Top Layer w0.254: v1(97.028,-10.541) R6_8.2
  Bottom Layer w0.254: v1(97.028,-10.541) 96.139,-9.652 96.139,-4.953 96.647,-4.445 U1_8.2
NetR6_9_2: R6_9.2 U1_9.2 | length 9.2
  Top Layer w0.254: v1(109.982,-10.541) R6_9.2
  Bottom Layer w0.254: v1(109.982,-10.541) 109.093,-9.652 109.093,-4.953 109.601,-4.445 U1_9.2
NetR6_10_2: R6_10.2 U1_10.2 | length 9.2
  Top Layer w0.254: v1(122.936,-10.541) R6_10.2
  Bottom Layer w0.254: v1(122.936,-10.541) 122.047,-9.652 122.047,-4.953 122.555,-4.445 U1_10.2
NetR7_1_2: R7_1.2 U1_1.1 | length 4
  Top Layer w0.254: v1(6.477,-3.175) 7.239,-2.413 R7_1.2
  Bottom Layer w0.254: v1(6.477,-3.175) U1_1.1
NetR7_2_2: R7_2.2 U1_2.1 | length 4
  Top Layer w0.254: v1(19.431,-3.175) 20.193,-2.413 R7_2.2
  Bottom Layer w0.254: v1(19.431,-3.175) U1_2.1
NetR7_3_2: R7_3.2 U1_3.1 | length 4
  Top Layer w0.254: v1(32.385,-3.175) 33.147,-2.413 R7_3.2
  Bottom Layer w0.254: v1(32.385,-3.175) U1_3.1
NetR7_4_2: R7_4.2 U1_4.1 | length 4
  Top Layer w0.254: v1(45.339,-3.175) 46.101,-2.413 R7_4.2
  Bottom Layer w0.254: v1(45.339,-3.175) U1_4.1
NetR7_5_2: R7_5.2 U1_5.1 | length 4
  Top Layer w0.254: v1(58.293,-3.175) 59.055,-2.413 R7_5.2
  Bottom Layer w0.254: v1(58.293,-3.175) U1_5.1
NetR7_6_2: R7_6.2 U1_6.1 | length 4
  Top Layer w0.254: v1(71.247,-3.175) 72.009,-2.413 R7_6.2
  Bottom Layer w0.254: v1(71.247,-3.175) U1_6.1
NetR7_7_2: R7_7.2 U1_7.1 | length 4
  Top Layer w0.254: v1(84.201,-3.175) 84.963,-2.413 R7_7.2
  Bottom Layer w0.254: v1(84.201,-3.175) U1_7.1
NetR7_8_2: R7_8.2 U1_8.1 | length 4
  Top Layer w0.254: v1(97.155,-3.175) 97.917,-2.413 R7_8.2
  Bottom Layer w0.254: v1(97.155,-3.175) U1_8.1
NetR7_9_2: R7_9.2 U1_9.1 | length 4
  Top Layer w0.254: v1(110.109,-3.175) 110.871,-2.413 R7_9.2
  Bottom Layer w0.254: v1(110.109,-3.175) U1_9.1
NetR7_10_2: R7_10.2 U1_10.1 | length 4
  Top Layer w0.254: v1(123.063,-3.175) 123.825,-2.413 R7_10.2
  Bottom Layer w0.254: v1(123.063,-3.175) U1_10.1
NetR8_1_2: R8_1.2 U1_1.15 | length 2.3
  Bottom Layer w0.254: U1_1.15 v1(3.937,-4.445)
NetR8_2_2: R8_2.2 U1_2.15 | length 2.3
  Bottom Layer w0.254: U1_2.15 v1(16.891,-4.445)
NetR8_3_2: R8_3.2 U1_3.15 | length 2.3
  Bottom Layer w0.254: U1_3.15 v1(29.845,-4.445)
NetR8_4_2: R8_4.2 U1_4.15 | length 2.3
  Bottom Layer w0.254: U1_4.15 v1(42.799,-4.445)
NetR8_5_2: R8_5.2 U1_5.15 | length 2.3
  Bottom Layer w0.254: U1_5.15 v1(55.753,-4.445)
NetR8_6_2: R8_6.2 U1_6.15 | length 2.3
  Bottom Layer w0.254: U1_6.15 v1(68.707,-4.445)
NetR8_7_2: R8_7.2 U1_7.15 | length 2.3
  Bottom Layer w0.254: U1_7.15 v1(81.661,-4.445)
NetR8_8_2: R8_8.2 U1_8.15 | length 2.3
  Bottom Layer w0.254: U1_8.15 v1(94.615,-4.445)
NetR8_9_2: R8_9.2 U1_9.15 | length 2.3
  Bottom Layer w0.254: U1_9.15 v1(107.569,-4.445)
NetR8_10_2: R8_10.2 U1_10.15 | length 2.3
  Bottom Layer w0.254: U1_10.15 v1(120.523,-4.445)
NetU1_1_9: pad.9@12.422,-5.715 U1_1.9 U1_2.14 | length 18.7
  Bottom Layer w0.254: U1_1.9 6.223,-12.065 6.833,-12.675 9.804,-12.675 10.973,-11.506 10.973,-7.061 12.319,-5.715 U1_2.14
NetU1_1_14: pad.9@-0.532,-5.715 U1_1.14 | length 2.3
  Bottom Layer w0.254: pad.9@-0.635,-5.715 U1_1.14
NetU1_2_9: pad.9@25.376,-5.715 U1_2.9 U1_3.14 | length 18.7
  Bottom Layer w0.254: U1_2.9 19.177,-12.065 19.787,-12.675 22.758,-12.675 23.927,-11.506 23.927,-7.061 25.273,-5.715 25.376,-5.715 U1_3.14
NetU1_3_9: pad.9@38.33,-5.715 U1_3.9 U1_4.14 | length 18.7
  Bottom Layer w0.254: U1_3.9 32.131,-12.065 32.741,-12.675 35.712,-12.675 36.881,-11.506 36.881,-7.061 38.227,-5.715 U1_4.14
NetU1_4_9: pad.9@51.284,-5.715 U1_4.9 U1_5.14 | length 18.7
  Bottom Layer w0.254: U1_4.9 45.085,-12.065 45.695,-12.675 48.666,-12.675 49.835,-11.506 49.835,-7.061 51.181,-5.715 U1_5.14
NetU1_5_9: pad.9@64.238,-5.715 U1_5.9 U1_6.14 | length 18.7
  Bottom Layer w0.254: U1_5.9 58.039,-12.065 58.649,-12.675 61.62,-12.675 62.789,-11.506 62.789,-7.061 64.135,-5.715 U1_6.14
NetU1_6_9: pad.9@77.192,-5.715 U1_6.9 U1_7.14 | length 18.7
  Bottom Layer w0.254: U1_6.9 70.993,-12.065 71.603,-12.675 74.574,-12.675 75.743,-11.506 75.743,-7.061 77.089,-5.715 U1_7.14
NetU1_7_9: pad.9@90.146,-5.715 U1_7.9 U1_8.14 | length 18.7
  Bottom Layer w0.254: U1_7.9 83.947,-12.065 84.557,-12.675 87.528,-12.675 88.697,-11.506 88.697,-7.061 90.043,-5.715 U1_8.14
NetU1_8_9: pad.9@103.1,-5.715 U1_8.9 U1_9.14 | length 18.7
  Bottom Layer w0.254: U1_8.9 96.901,-12.065 97.511,-12.675 100.482,-12.675 101.651,-11.506 101.651,-7.061 102.997,-5.715 U1_9.14
NetU1_9_9: pad.9@116.054,-5.715 U1_9.9 U1_10.14 | length 18.7
  Bottom Layer w0.254: U1_9.9 109.855,-12.065 110.465,-12.675 113.436,-12.675 114.605,-11.506 114.605,-7.061 115.951,-5.715 U1_10.14
NetU1_10_9: U1_10.9
SHCP: pad.11 U1_1.11 U1_2.11 U1_3.11 U1_4.11 U1_5.11 U1_6.11 U1_7.11 U1_8.11 U1_9.11 U1_10.11 | length 128.6
  Top Layer w0.254: v1(4.191,-9.525) 4.572,-9.144 12.319,-9.144 v2(12.878,-9.703) ; v1(17.145,-9.525) 17.526,-9.144 25.273,-9.144 v2(25.832,-9.703) ; v1(30.099,-9.525) 30.48,-9.144 38.227,-9.144 v2(38.786,-9.703) ; v1(43.053,-9.525) 43.434,-9.144 51.181,-9.144 v2(51.74,-9.703) ; v1(56.007,-9.525) 56.388,-9.144 64.135,-9.144 v2(64.694,-9.703) ; v1(68.961,-9.525) 69.342,-9.144 77.089,-9.144 v2(77.648,-9.703) ; v1(81.915,-9.525) 82.296,-9.144 90.043,-9.144 v2(90.602,-9.703) ; v1(94.869,-9.525) 95.25,-9.144 102.997,-9.144 v2(103.556,-9.703) ; v1(107.823,-9.525) 108.204,-9.144 115.951,-9.144 v2(116.51,-9.703)
  Bottom Layer w0.254: pad.11@-0.533,-10.058 0,-9.525 U1_1.11 v1(4.191,-9.525) ; pad.11@12.421,-10.058 12.954,-9.525 U1_2.11 v1(17.145,-9.525) ; pad.11@25.375,-10.058 25.908,-9.525 U1_3.11 v1(30.099,-9.525) ; pad.11@38.329,-10.058 38.862,-9.525 U1_4.11 v1(43.053,-9.525) ; pad.11@51.283,-10.058 51.816,-9.525 v1(56.007,-9.525) ; pad.11@64.237,-10.058 64.77,-9.525 v1(68.961,-9.525) ; pad.11@77.191,-10.058 77.724,-9.525 v1(81.915,-9.525) ; pad.11@90.145,-10.058 90.678,-9.525 v1(94.869,-9.525) ; pad.11@103.099,-10.058 103.632,-9.525 v1(107.823,-9.525) ; pad.11@116.053,-10.058 116.586,-9.525 U1_10.11
STCP: pad.10 U1_1.12 U1_2.12 U1_3.12 U1_4.12 U1_5.12 U1_6.12 U1_7.12 U1_8.12 U1_9.12 U1_10.12 | length 124.6
  Top Layer w0.254: v1(4.191,-8.255) 4.572,-8.636 v2@12.7,-8.636 ; v1(17.145,-8.255) 17.526,-8.636 25.756,-8.636 v2(25.781,-8.611) ; v1(30.099,-8.255) 30.48,-8.636 v2@38.71,-8.636 ; v1(43.053,-8.255) 43.434,-8.636 v2@51.664,-8.636 ; v1(56.007,-8.255) 56.388,-8.636 v2@64.618,-8.636 ; v1(68.961,-8.255) 69.342,-8.636 v2@77.572,-8.636 ; v1(81.915,-8.255) 82.296,-8.636 v2@90.526,-8.636 ; v1(94.869,-8.255) 95.25,-8.636 v2@103.48,-8.636 ; v1(107.823,-8.255) 108.204,-8.636 v2@116.434,-8.636
  Bottom Layer w0.254: pad.10@-0.635,-8.255 U1_1.12 v1(4.191,-8.255) ; pad.10@12.319,-8.255 U1_2.12 v1(17.145,-8.255) ; pad.10@25.273,-8.255 25.376,-8.255 U1_3.12 v1(30.099,-8.255) ; pad.10@38.227,-8.255 U1_4.12 v1(43.053,-8.255) ; pad.10@51.181,-8.255 v1(56.007,-8.255) ; pad.10@64.135,-8.255 v1(68.961,-8.255) ; pad.10@77.089,-8.255 v1(81.915,-8.255) ; pad.10@90.043,-8.255 v1(94.869,-8.255) ; pad.10@102.997,-8.255 v1(107.823,-8.255) ; pad.10@115.951,-8.255 U1_10.12
  other v2: 12.827,-8.611 38.735,-8.611 51.689,-8.611 64.643,-8.611 77.597,-8.611 90.551,-8.611 103.505,-8.611 116.459,-8.611

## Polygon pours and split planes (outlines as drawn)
GND on Bottom Layer "Bottom Layer-No Net" (solid, pour order 0): -1.524,-1.321 126.746,-1.321 126.746,-13.589 -1.854,-13.589 -2.921,-12.522 -2.921,-2.718
GND on Top Layer "Bottom Layer-No Net" (solid, pour order 4): -2.032,-1.321 126.746,-1.321 126.746,-13.589 -2.032,-13.589

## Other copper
Bottom Layer:
  pour cut-out: 8.247,-1.662 ccw(c8.501,-1.662) 8.501,-1.916 ccw(c8.501,-1.662) 8.755,-1.662 ccw(c8.501,-1.662) 8.501,-1.408 ccw(c8.501,-1.662)
  pour cut-out: 21.201,-1.662 ccw(c21.455,-1.662) 21.455,-1.916 ccw(c21.455,-1.662) 21.709,-1.662 ccw(c21.455,-1.662) 21.455,-1.408 ccw(c21.455,-1.662)
  pour cut-out: 34.155,-1.662 ccw(c34.409,-1.662) 34.409,-1.916 ccw(c34.409,-1.662) 34.663,-1.662 ccw(c34.409,-1.662) 34.409,-1.408 ccw(c34.409,-1.662)
  pour cut-out: 47.109,-1.662 ccw(c47.363,-1.662) 47.363,-1.916 ccw(c47.363,-1.662) 47.617,-1.662 ccw(c47.363,-1.662) 47.363,-1.408 ccw(c47.363,-1.662)
  pour cut-out: 60.063,-1.662 ccw(c60.317,-1.662) 60.317,-1.916 ccw(c60.317,-1.662) 60.571,-1.662 ccw(c60.317,-1.662) 60.317,-1.408 ccw(c60.317,-1.662)
  pour cut-out: 73.017,-1.662 ccw(c73.271,-1.662) 73.271,-1.916 ccw(c73.271,-1.662) 73.525,-1.662 ccw(c73.271,-1.662) 73.271,-1.408 ccw(c73.271,-1.662)
  pour cut-out: 85.971,-1.662 ccw(c86.225,-1.662) 86.225,-1.916 ccw(c86.225,-1.662) 86.479,-1.662 ccw(c86.225,-1.662) 86.225,-1.408 ccw(c86.225,-1.662)
  pour cut-out: 98.925,-1.662 ccw(c99.179,-1.662) 99.179,-1.916 ccw(c99.179,-1.662) 99.433,-1.662 ccw(c99.179,-1.662) 99.179,-1.408 ccw(c99.179,-1.662)
  pour cut-out: 111.879,-1.662 ccw(c112.133,-1.662) 112.133,-1.916 ccw(c112.133,-1.662) 112.387,-1.662 ccw(c112.133,-1.662) 112.133,-1.408 ccw(c112.133,-1.662)
  pour cut-out: 124.833,-1.662 ccw(c125.087,-1.662) 125.087,-1.916 ccw(c125.087,-1.662) 125.341,-1.662 ccw(c125.087,-1.662) 125.087,-1.408 ccw(c125.087,-1.662)

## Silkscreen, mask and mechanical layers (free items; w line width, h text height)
Mechanical 10:
  the board outline again, w0.1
